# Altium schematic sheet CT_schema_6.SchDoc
size 254 x 245 mm
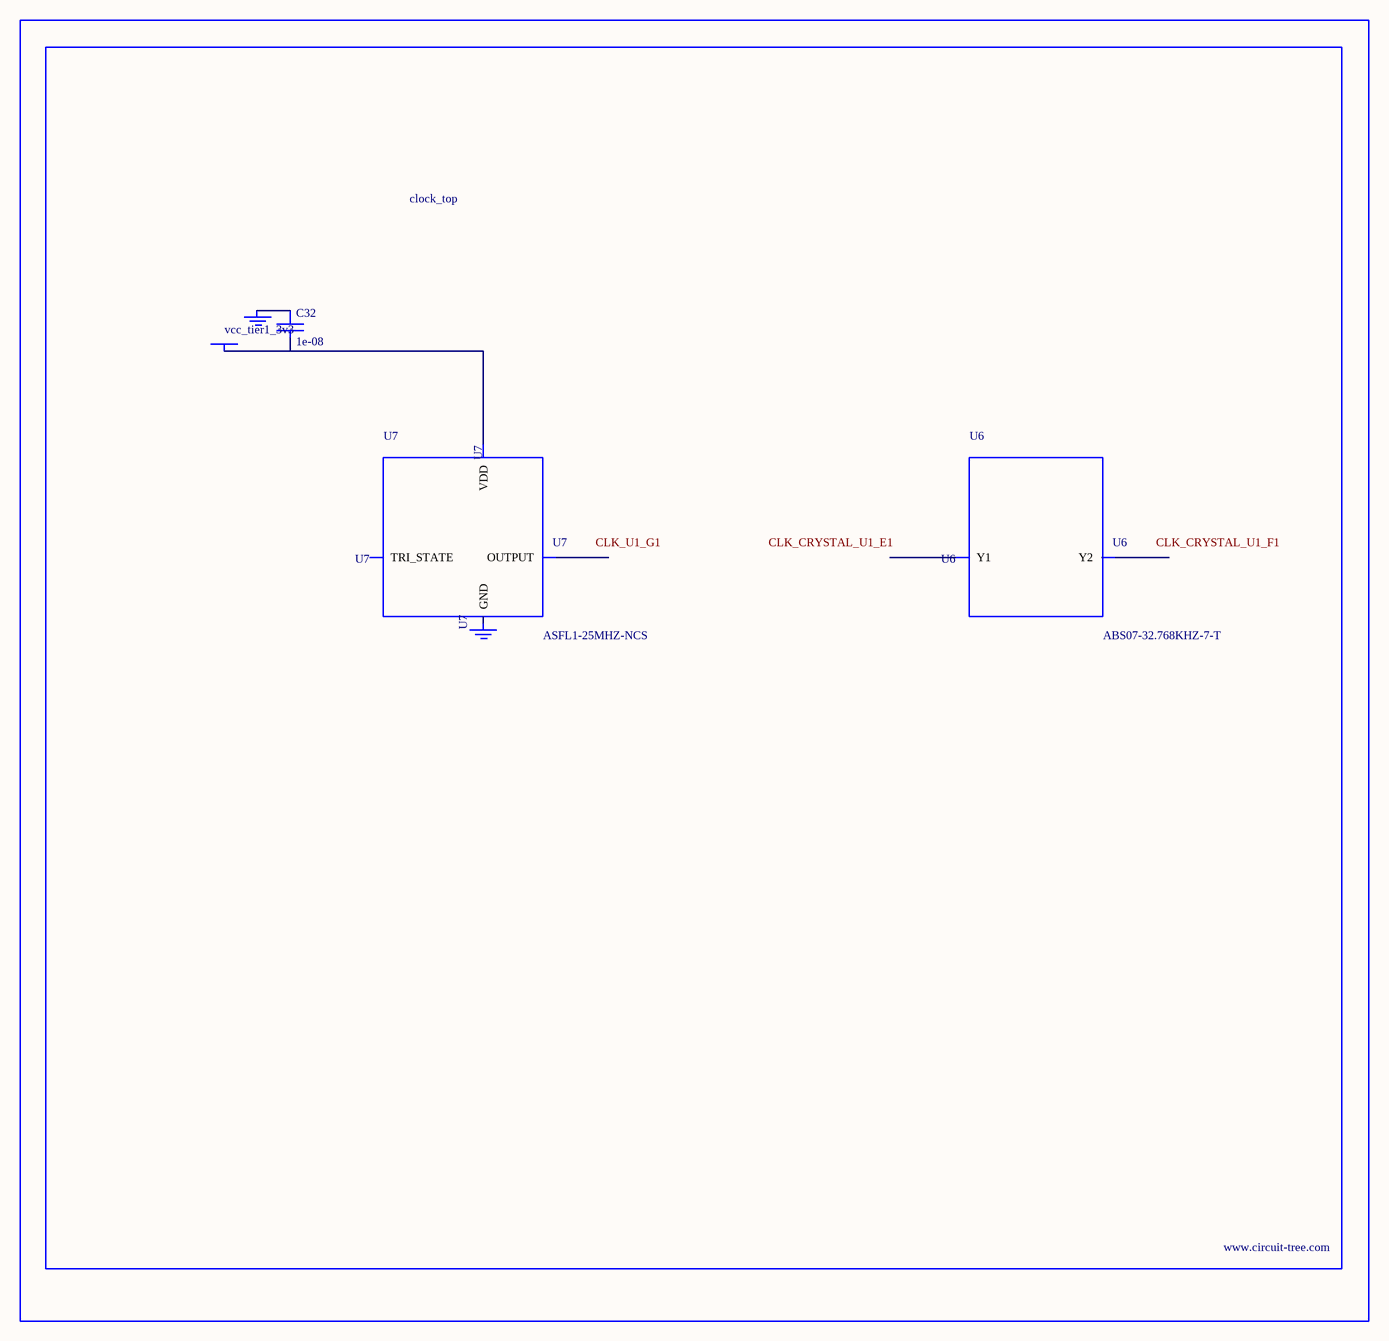
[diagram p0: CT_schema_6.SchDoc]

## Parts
BORDER5  (no value)
C32  1e-08  [C0402]
GND_INSTANCE_5_0  (no value)
GND_INSTANCE_5_1  (no value)
POWER_INSTANCE_5_0  vcc_tier1_3v3
U6  ABS07-32.768KHZ-7-T  [ABS07-32.768KHZ-7-T]
U7  ASFL1-25MHZ-NCS  [ASFL1]

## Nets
NetC32_1: C32.1 GND_INSTANCE_5_0.0(GND)
NetC32_2: C32.2 POWER_INSTANCE_5_0.0(PWR) U7.4(VDD)

Not connected (* = marked no-connect by the designer): GND_INSTANCE_5_1 0(GND); U6 1(Y1) 2(Y2); U7 1(TRI_STATE) 2(GND) 3(OUTPUT)

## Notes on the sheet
- Labels drawn without touching a wire or pin: CLK_CRYSTAL_U1_E1, CLK_CRYSTAL_U1_F1, CLK_U1_G1

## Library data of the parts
BORDER5 = BORDER_PAGE5
C32 = C0402C103K3RAC
GND_INSTANCE_5_0 GND_INSTANCE_5_1 = GND
POWER_INSTANCE_5_0 = PWR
